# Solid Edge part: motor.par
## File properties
Author: ptcarter
Template: normal.par
Last saved by: ptcarter
Revision: 29
Application: Solid Edge
Accuracy: 0.99
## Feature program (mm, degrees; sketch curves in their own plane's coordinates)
sketch for "unnamed RevolvedProtrusion 1" plane through (0, 0, 0) normal (1, 0, 0) x-axis (0, 1, 0)
  line (0, 52.1551) -> (-30, 52.1551)
  line (-30, 52.1551) -> (-30, 42.1551)
  line (-30, 42.1551) -> (-29, 42.1551)
  line (-29, 42.1551) -> (-29, 17.1551)
  line (-29, 17.1551) -> (-30, 17.1551)
  line (-30, 17.1551) -> (-30, 7.1551)
  line (-30, 7.1551) -> (0, 7.1551)
revolve "unnamed RevolvedProtrusion 1" add finite 360 deg about sketch line (0, 7.1551) -> (0, 52.1551)
fillet "unnamed Round 1"
thinwall "Thinwall_1"  Thickness = 1 mm
sketch for "ExtrudedProtrusion_4" plane through (0, 0, 17.1551) normal (0, 0, 1) x-axis (1, 0, 0)
  line (-6, 21.166) -> (-6, 34)
  arc centre (0, 34) radius 6 from (-6, 34) to (6, 34) cw
  line (6, 34) -> (6, 21.166)
  line (6, 21.166) -> (-6, 21.166)
extrude "ExtrudedProtrusion_4" add finite 18 along -normal
pattern "unnamed Pattern 1" of "ExtrudedProtrusion_4"
extrude "unnamed Protrusion 1" add finite 18
extrude "unnamed Protrusion 2" add finite 18
extrude "unnamed Protrusion 3" add finite 18
sketch for "unnamed Cutout 1" plane through (0, -30.583, -0.8449) normal (0, 0, -1) x-axis (1, 0, 0)
  circle centre (0, -30.583) radius 30
extrude "unnamed Cutout 1" cut to key point along -normal
fillet "Round_4" radius 5
fillet "Round_7" radius 5
fillet "Round_8" radius 5
sketch for "Hole_1" plane through (0, -34.6969, -0.8449) normal (0, 0, -1) x-axis (1, 0, 0)
  hole centre (0, -0.6969) bore radius 2.5
hole "Hole_1" diameter 5 finite
sketch for "unnamed Hole 1" plane through (0, -34.6969, -0.8449) normal (0, 0, -1) x-axis (1, 0, 0)
  hole centre (-34, -34.6969) bore radius 2.5
hole "unnamed Hole 1" finite
sketch for "unnamed Hole 2" plane through (0, -34.6969, -0.8449) normal (0, 0, -1) x-axis (1, 0, 0)
  hole centre (34, -34.6969) bore radius 2.5
hole "unnamed Hole 2" finite
sketch for "unnamed Hole 3" plane through (0, -34.6969, -0.8449) normal (0, 0, -1) x-axis (1, 0, 0)
  hole centre (0, -68.6969) bore radius 2.5
hole "unnamed Hole 3" finite
pattern "unnamed Pattern 2" of "Hole_1", "unnamed Hole 1", "unnamed Hole 2", "unnamed Hole 3"
sketch for "unnamed RevolvedProtrusion 2" plane through (0, 0, 0) normal (1, 0, 0) x-axis (0, 1, 0)
  line (0, -4.3449) -> (-2, -4.3449)
  line (-2, -4.3449) -> (-2, 5.6551)
  line (-2, 5.6551) -> (-8, 5.6551)
  line (-8, 5.6551) -> (-8, 53.6551)
  line (-8, 53.6551) -> (-2, 53.6551)
  line (-2, 53.6551) -> (-2, 63.6551)
  line (-2, 63.6551) -> (0, 63.6551)
revolve "unnamed RevolvedProtrusion 2" add full turn 360 deg about sketch line (0, 63.6551) -> (0, -4.3449)
sketch for "unnamed Cutout 2" plane through (0, 0, 7.1551) normal (0, 0, -1) x-axis (1, 0, 0)
  arc centre (0, 0) radius 10 from (-0.3724, 9.9931) to (0.3724, 9.9931) cw
  line (0.3724, 9.9931) -> (1.2445, 19.9612)
  arc centre (0, 0) radius 20 from (-1.2445, 19.9612) to (1.2445, 19.9612) cw
  line (-0.3724, 9.9931) -> (-1.2445, 19.9612)
extrude "unnamed Cutout 2" cut through along -normal
pattern "unnamed Pattern 3" of "unnamed Cutout 2"
extrude "unnamed Cutout 3" cut through
extrude "unnamed Cutout 4" cut through
extrude "unnamed Cutout 5" cut through
extrude "unnamed Cutout 6" cut through
extrude "unnamed Cutout 7" cut through
extrude "unnamed Cutout 8" cut through
extrude "unnamed Cutout 9" cut through
extrude "unnamed Cutout 10" cut through
extrude "unnamed Cutout 11" cut through
extrude "unnamed Cutout 12" cut through
extrude "unnamed Cutout 13" cut through
extrude "unnamed Cutout 14" cut through
extrude "unnamed Cutout 15" cut through
extrude "unnamed Cutout 16" cut through
extrude "unnamed Cutout 17" cut through
extrude "unnamed Cutout 18" cut through
extrude "unnamed Cutout 19" cut through
extrude "unnamed Cutout 20" cut through
extrude "unnamed Cutout 21" cut through
extrude "unnamed Cutout 22" cut through
extrude "unnamed Cutout 23" cut through
extrude "unnamed Cutout 24" cut through
extrude "unnamed Cutout 25" cut through
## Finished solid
Body 1: solid body, 327 faces, 878 edges, 554 vertices.
  Faces by surface: plane 143, cylinder 134, blend 32, torus 18
  Edges by curve: line 471, circle 316, intersection 91
Bounding box of the edges (mm; curved faces can reach further): 80.000 x 80.000 x 68.000, from (-40, -40, -4.3449) to (40, 40, 63.6551).
Cylindrical faces by radius (mm): R2 x2, R2.5 x4, R5 x9, R6 x4, R8 x3, R10 x48, R20 x48, R28 x1, R29 x6, R30 x9
Toroidal faces (ring radius, tube radius in mm): R1 r5 x4, R22 r7 x5, R22 r8 x5, R25 r5 x4
Planar faces by outward normal: +x 5, +y 5, +z 10, -x 5, -y 5, -z 17, oblique 96
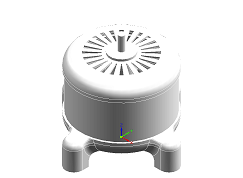
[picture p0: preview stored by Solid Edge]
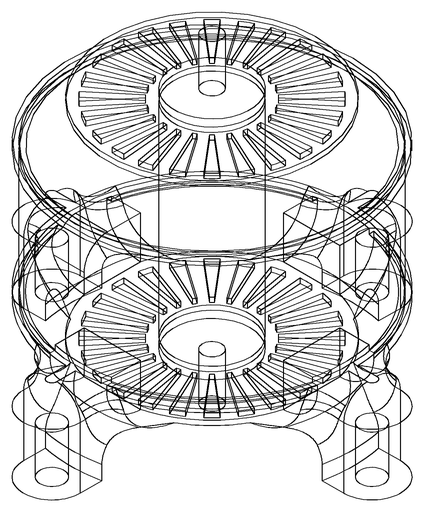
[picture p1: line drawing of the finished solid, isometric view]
